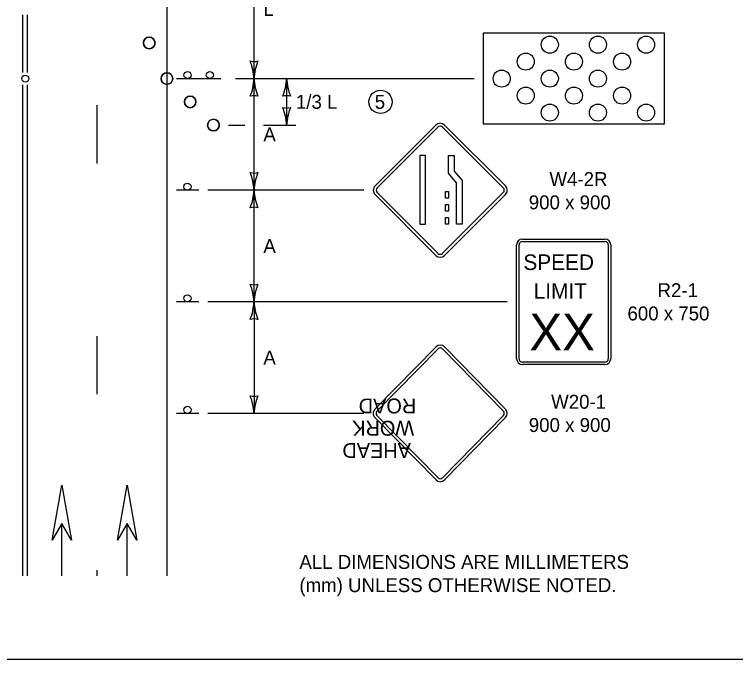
# Model space of a CAD drawing. Extents: x 49991.4 to 50021, y 49987.6 to 50011.4.
# Drawn here: x 50010.547 to 50013.648, y 49987.799 to 49990.574 of the extents above; entities that cross this region are included whole.
import ezdxf

# ---------------------------------------------------------------- set-up
doc = ezdxf.new("R2010")
doc.units = 0
for name, color, linetype in [('Level 1', 7, 'Continuous'), ('Level 2', 7, 'Continuous'), ('Level 25', 7, 'Continuous'), ('Level 3', 7, 'Continuous'), ('S_BOT_RW_TTL_Sheet_No_DF', 7, 'Continuous')]:
    doc.layers.add(name, color=color, linetype=linetype)

# ---------------------------------------------------------------- blocks, each defined once
blk = doc.blocks.new('ARR')
at = {"layer": 'Level 3'}
for centre, radius, start, end in [((1.53, 37.02), 37.05, 247.456, 267.6395), ((-21.37, 0), 9.13, 342.1388, 17.8612), ((1.92, -38.79), 38.83, 92.8273, 112.0772)]:
    blk.add_arc(centre, radius, start, end, dxfattribs=at)

msp = doc.modelspace()

# ---------------------------------------------------------------- linework, layer by layer
at = {"layer": 'Level 1'}
for p, q in [((50011.2032, 49988.1586), (50011.2032, 49992.9404)), ((50010.5832, 49990.3239), (50010.5832, 49990.5715)), ((50010.6032, 49990.3239), (50010.6032, 49990.5715)), ((50010.5832, 49988.1586), (50010.5832, 49990.2715)), ((50010.6032, 49988.1586), (50010.6032, 49990.2715)), ((50011.2432, 49990.2977), (50011.3392, 49990.2977)), ((50011.3392, 49990.2977), (50011.4352, 49990.2977)), ((50010.9028, 49989.9331), (50010.9028, 49990.1831)), ((50011.3392, 49989.8177), (50011.2432, 49989.8177)), ((50012.7318, 49989.6077), (50013.0862, 49989.6077)), ((50012.7318, 49989.5972), (50013.0862, 49989.5972)), ((50012.909, 49989.6077), (50012.909, 49989.6077)), ((50012.7065, 49989.093), (50012.7065, 49989.5824)), ((50012.717, 49989.093), (50012.717, 49989.5824)), ((50013.101, 49989.5824), (50013.101, 49989.093)), ((50013.1115, 49989.5824), (50013.1115, 49989.093)), ((50011.3392, 49989.3377), (50011.2432, 49989.3377)), ((50010.9033, 49988.9404), (50010.9033, 49989.1904)), ((50012.0972, 49988.8757), (50012.36, 49989.144)), ((50012.1059, 49988.8671), (50012.3687, 49989.1354)), ((50012.3872, 49989.1354), (50012.65, 49988.8671)), ((50012.3959, 49989.144), (50012.6587, 49988.8757)), ((50013.0862, 49989.0782), (50012.7318, 49989.0782)), ((50013.0862, 49989.0677), (50012.7318, 49989.0677)), ((50011.3392, 49988.8577), (50011.2432, 49988.8577)), ((50012.3687, 49988.5802), (50012.1059, 49988.8484)), ((50012.65, 49988.8484), (50012.3872, 49988.5802)), ((50012.36, 49988.5716), (50012.0972, 49988.8398)), ((50012.6587, 49988.8398), (50012.3959, 49988.5716)), ((50010.7506, 49988.1586), (50010.7506, 49988.3845)), ((50010.751, 49988.1586), (50010.751, 49988.3845)), ((50011.0316, 49988.1586), (50011.0316, 49988.3845)), ((50011.032, 49988.1586), (50011.032, 49988.3845)), ((50010.9028, 49988.1586), (50010.9028, 49988.1831))]:
    msp.add_line(p, q, dxfattribs=at)
for points in [[(49999.3835, 49998.9992), (50016.7501, 49998.9992), (50016.7501, 49987.7988), (49999.3835, 49987.7988)], [(50012.5634, 49990.1027), (50013.3431, 49990.1027), (50013.3431, 49990.4927), (50012.5634, 49990.4927)], [(50012.5634, 49990.1027), (50013.3431, 49990.1027), (50013.3431, 49990.4927), (50012.5634, 49990.4927)], [(50010.709, 49988.3122), (50010.7506, 49988.5487), (50010.7926, 49988.3122), (50010.7506, 49988.3844)], [(50010.99, 49988.3122), (50011.0316, 49988.5487), (50011.0736, 49988.3122), (50011.0316, 49988.3844)]]:
    msp.add_lwpolyline(points, close=True, dxfattribs=at)
for centre, radius in [((50011.1265, 49990.451), 0.025), ((50012.8495, 49990.4437), 0.0366), ((50012.8495, 49990.4437), 0.0366), ((50013.0566, 49990.4437), 0.0366), ((50013.0566, 49990.4437), 0.0366), ((50013.2637, 49990.4437), 0.0366), ((50013.2637, 49990.4437), 0.0366), ((50012.7459, 49990.3706), 0.0366), ((50012.7459, 49990.3706), 0.0366), ((50012.9531, 49990.3706), 0.0366), ((50012.9531, 49990.3706), 0.0366), ((50013.1602, 49990.3706), 0.0366), ((50013.1602, 49990.3706), 0.0366), ((50012.6424, 49990.2975), 0.0366), ((50012.6424, 49990.2975), 0.0366), ((50012.8495, 49990.2975), 0.0366), ((50012.8495, 49990.2975), 0.0366), ((50013.0566, 49990.2975), 0.0366), ((50013.0566, 49990.2975), 0.0366), ((50010.5932, 49990.2977), 0.015), ((50011.2027, 49990.2977), 0.025), ((50011.2912, 49990.3129), 0.0152), ((50011.3872, 49990.3129), 0.0152), ((50012.7459, 49990.2244), 0.0366), ((50012.7459, 49990.2244), 0.0366), ((50012.9531, 49990.2244), 0.0366), ((50012.9531, 49990.2244), 0.0366), ((50013.1602, 49990.2244), 0.0366), ((50013.1602, 49990.2244), 0.0366), ((50011.3027, 49990.1977), 0.025), ((50012.8495, 49990.1513), 0.0366), ((50012.8495, 49990.1513), 0.0366), ((50013.0566, 49990.1513), 0.0366), ((50013.0566, 49990.1513), 0.0366), ((50013.2637, 49990.1513), 0.0366), ((50013.2637, 49990.1513), 0.0366), ((50011.4026, 49990.0977), 0.025), ((50011.2911, 49989.8329), 0.0152), ((50011.2911, 49989.3529), 0.0152), ((50011.2911, 49988.8729), 0.0152)]:
    msp.add_circle(centre, radius, dxfattribs=at)
for centre, radius, start, end in [((50011.1265, 49990.451), 0.025, 0, 180), ((50011.1265, 49990.451), 0.025, 180, 0), ((50011.2027, 49990.2977), 0.025, 0, 180), ((50011.2027, 49990.2977), 0.025, 180, 0), ((50011.3027, 49990.1977), 0.025, 0, 180), ((50011.3027, 49990.1977), 0.025, 180, 0), ((50011.4026, 49990.0977), 0.025, 0, 180), ((50011.4026, 49990.0977), 0.025, 180, 0), ((50012.7318, 49989.5824), 0.0253, 90, 180), ((50012.7318, 49989.5824), 0.0148, 90, 180), ((50013.0862, 49989.5824), 0.0253, 0, 90), ((50013.0862, 49989.5824), 0.0148, 0, 90), ((50012.7318, 49989.093), 0.0253, 180, 270), ((50012.7318, 49989.093), 0.0148, 180, 270), ((50013.0862, 49989.093), 0.0148, 270, 360), ((50013.0862, 49989.093), 0.0253, 270, 360)]:
    msp.add_arc(centre, radius, start, end, dxfattribs=at)
for centre, major_axis, ratio, start_param, end_param in [((50012.378, 49989.1259), (0, 0.0255), 0.98963, 5.497787, 7.068583), ((50012.378, 49989.1259), (0, 0.0132), 0.98, 5.497787, 7.068583), ((50012.1151, 49988.8577), (0, 0.0255), 0.98963, 0.785394, 2.356194), ((50012.6408, 49988.8577), (0, 0.0255), 0.98963, 3.926991, 5.497787), ((50012.1151, 49988.8577), (0, 0.0132), 0.98, 0.785394, 2.356194), ((50012.6408, 49988.8577), (0, 0.0132), 0.98, 3.926991, 5.497787), ((50012.378, 49988.5895), (0, -0.0255), 0.98963, 5.497795, 7.068583), ((50012.378, 49988.5895), (0, -0.0132), 0.98, 5.497795, 7.068583)]:
    msp.add_ellipse(centre, major_axis=major_axis, ratio=ratio, start_param=start_param, end_param=end_param, dxfattribs=at)
at = {"layer": 'Level 2'}
msp.add_circle((50012.1214, 49990.1976), 0.0501, dxfattribs=at)
at = {"layer": 'Level 25'}
for p, q in [((50012.0976, 49989.8364), (50012.3593, 49990.0981)), ((50012.3681, 49990.0892), (50012.1064, 49989.8276)), ((50012.3681, 49990.0892), (50012.3681, 49990.0892)), ((50012.6495, 49989.8276), (50012.3878, 49990.0892)), ((50012.3966, 49990.0981), (50012.6583, 49989.8364)), ((50012.3146, 49989.9668), (50012.2902, 49989.9668)), ((50012.2902, 49989.9668), (50012.2902, 49989.6717)), ((50012.3146, 49989.6717), (50012.3146, 49989.9668)), ((50012.1064, 49989.8078), (50012.3681, 49989.5462)), ((50012.3878, 49989.5462), (50012.6495, 49989.8078)), ((50012.3593, 49989.5373), (50012.0976, 49989.799)), ((50012.6583, 49989.799), (50012.3966, 49989.5373)), ((50012.2902, 49989.6717), (50012.3146, 49989.6717))]:
    msp.add_line(p, q, dxfattribs=at)
msp.add_lwpolyline([(50012.3308, 49989.6532), (50012.331, 49989.6534)], dxfattribs=at)
for centre, radius, start, end in [((50012.378, 49990.0794), 0.0264, 45.0001, 134.9999), ((50012.378, 49990.0794), 0.014, 45.0001, 134.9999), ((50012.1163, 49989.8177), 0.0264, 134.9999, 225.0001), ((50012.6396, 49989.8177), 0.0264, 314.9999, 45.0001), ((50012.1163, 49989.8177), 0.014, 134.9999, 225.0001), ((50012.6396, 49989.8177), 0.014, 314.9999, 45.0001), ((50012.378, 49989.556), 0.0264, 225.0001, 314.9999), ((50012.378, 49989.556), 0.014, 225.0001, 314.9999)]:
    msp.add_arc(centre, radius, start, end, dxfattribs=at)
at = {"layer": 'Level 3'}
for p, q in [((50011.5774, 49990.2977), (50011.5774, 49990.8977)), ((50011.497, 49990.2977), (50012.5234, 49990.2977)), ((50011.5774, 49989.8177), (50011.5774, 49990.2977)), ((50011.7174, 49990.2977), (50011.7174, 49990.0977)), ((50011.4676, 49990.0977), (50011.5374, 49990.0977)), ((50011.6174, 49990.0977), (50011.7574, 49990.0977)), ((50012.0498, 49989.8177), (50011.3792, 49989.8177)), ((50011.5774, 49989.3377), (50011.5774, 49989.8177)), ((50012.6665, 49989.3377), (50011.3792, 49989.3377)), ((50011.5774, 49989.3377), (50011.5774, 49988.8577)), ((50012.0498, 49988.8577), (50011.3792, 49988.8577))]:
    msp.add_line(p, q, dxfattribs=at)
for centre, radius, start, end in [((50011.5774, 49990.4259), 0.0548, 252.1388, 287.8612), ((50011.3447, 49990.2862), 0.233, 2.8273, 22.0772), ((50011.7996, 49990.2885), 0.2223, 157.456, 177.6395), ((50011.4953, 49990.3069), 0.2223, 337.456, 357.6395), ((50011.9502, 49990.3092), 0.233, 182.8273, 202.0772), ((50011.7174, 49990.1695), 0.0548, 72.1388, 107.8612), ((50011.7174, 49990.2259), 0.0548, 252.1388, 287.8612), ((50011.4847, 49990.0862), 0.233, 2.8273, 22.0772), ((50011.9396, 49990.0885), 0.2223, 157.456, 177.6395)]:
    msp.add_arc(centre, radius, start, end, dxfattribs=at)
at = {"layer": 'S_BOT_RW_TTL_Sheet_No_DF'}
for p, q in [((50012.4133, 49989.8905), (50012.4133, 49989.9668)), ((50012.4133, 49989.9668), (50012.4377, 49989.9668)), ((50012.4377, 49989.9668), (50012.4377, 49989.8995)), ((50012.4377, 49989.8995), (50012.4727, 49989.8589)), ((50012.4482, 49989.8498), (50012.4133, 49989.8905)), ((50012.4482, 49989.6717), (50012.4482, 49989.8498)), ((50012.4727, 49989.8589), (50012.4727, 49989.6717)), ((50012.4005, 49989.7837), (50012.4005, 49989.8117)), ((50012.4005, 49989.8117), (50012.4134, 49989.8117)), ((50012.4134, 49989.8117), (50012.4134, 49989.7837)), ((50012.4134, 49989.7837), (50012.4005, 49989.7837)), ((50012.4005, 49989.7277), (50012.4005, 49989.7557)), ((50012.4005, 49989.7557), (50012.4134, 49989.7557)), ((50012.4134, 49989.7557), (50012.4134, 49989.7277)), ((50012.4134, 49989.7277), (50012.4005, 49989.7277)), ((50012.4002, 49989.6717), (50012.4002, 49989.6997)), ((50012.4002, 49989.6997), (50012.4131, 49989.6997)), ((50012.4131, 49989.6997), (50012.4131, 49989.6717)), ((50012.4131, 49989.6717), (50012.4002, 49989.6717)), ((50012.4727, 49989.6717), (50012.4482, 49989.6717))]:
    msp.add_line(p, q, dxfattribs=at)

# ---------------------------------------------------------------- block references
at = {"layer": 'Level 2', "xscale": 0.006, "yscale": 0.006}
for p, rotation in [((50011.5774, 49990.2977), 90), ((50011.5774, 49989.8177), -90), ((50011.5774, 49989.8177), 90), ((50011.5774, 49989.3377), -90), ((50011.5774, 49989.3377), 90), ((50011.5774, 49988.8577), -90)]:
    msp.add_blockref('ARR', p, dxfattribs=dict(at, rotation=rotation))

# ---------------------------------------------------------------- texts
at = {"layer": 'Level 1'}
for s, height, p in [('SPEED', 0.06695, (50012.7359, 49989.4745)), ('LIMIT', 0.06695, (50012.7802, 49989.3507)), ('XX', 0.15772, (50012.7619, 49989.1288))]:
    msp.add_text(s, height=height, dxfattribs=at).set_placement(p)
for s, p in [('ROAD', (50012.2747, 49988.9217)), ('WORK', (50012.2657, 49988.8258)), ('AHEAD', (50012.2521, 49988.7299))]:
    msp.add_text(s, height=0.06395, rotation=180, dxfattribs=at).set_placement(p)
at = {"layer": 'Level 2'}
for s, p in [('L', (50011.6174, 49990.5677)), ('1/3 L', (50011.7574, 49990.1677)), ('5', (50012.0964, 49990.1676)), ('A', (50011.6174, 49990.0277)), ('W4-2R', (50012.8479, 49989.8354)), ('900 x 900', (50012.7591, 49989.7354)), ('A', (50011.6174, 49989.5477)), ('R2-1', (50013.3127, 49989.3577)), ('600 x 750', (50013.1835, 49989.2577)), ('A', (50011.6174, 49989.0677)), ('W20-1', (50012.8551, 49988.8777)), ('900 x 900', (50012.7591, 49988.7777)), ('ALL DIMENSIONS ARE MILLIMETERS', (50011.7723, 49988.1889)), ('(mm) UNLESS OTHERWISE NOTED.', (50011.7723, 49988.0889))]:
    msp.add_text(s, height=0.06, dxfattribs=at).set_placement(p)

doc.saveas('drawing.dxf')
